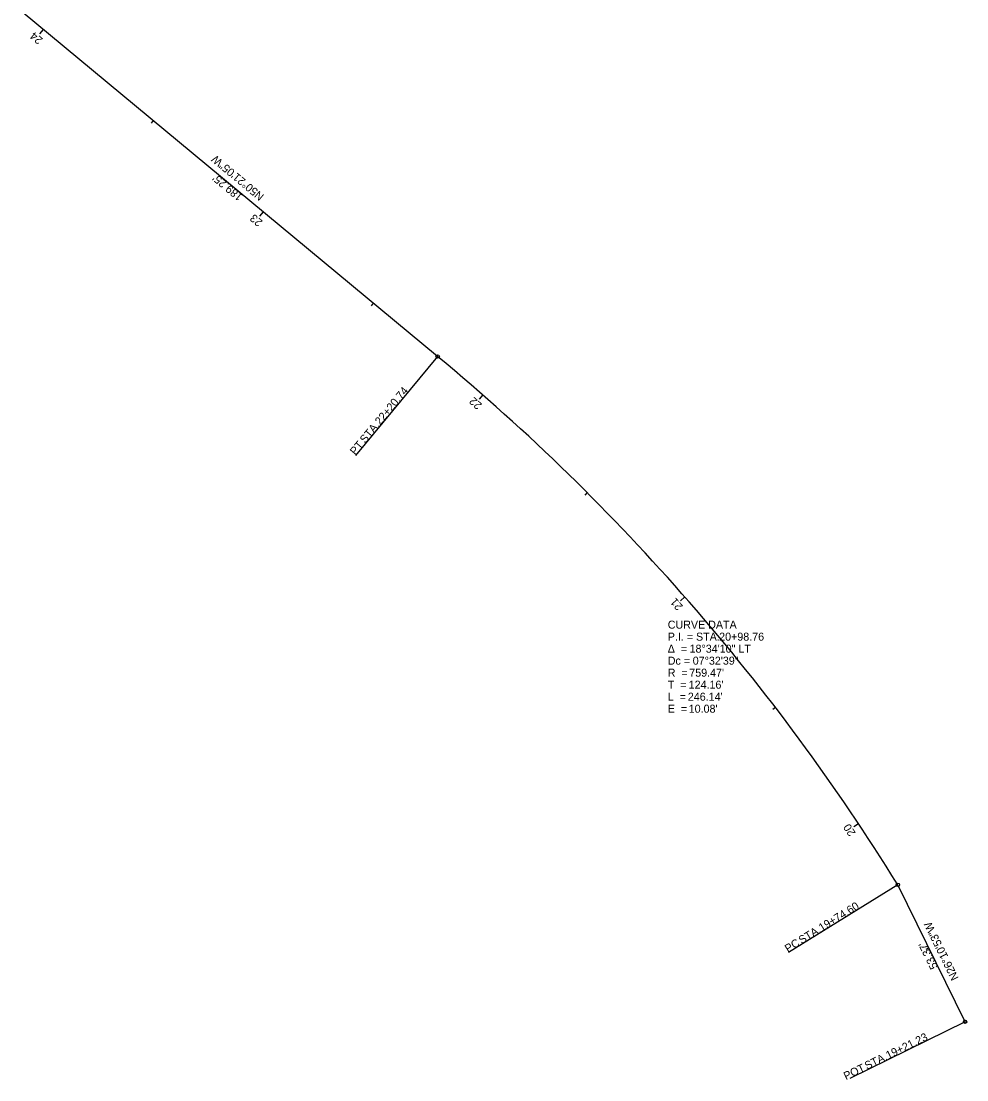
# Model space of a CAD drawing. Extents: x 127563 to 127989, y 300983 to 302508.
# Drawn here: x 127657.7 to 127988.6, y 300983 to 301353.2 of the extents above; entities that cross this region are included whole.
import ezdxf

# ---------------------------------------------------------------- set-up
doc = ezdxf.new("R2010")
doc.units = 0
for name, color, linetype in [('DR_X_Cells', 7, 'Continuous'), ('GK_Drainage_Nodes', 7, 'Continuous'), ('RS_Raster1', 7, 'Continuous'), ('SC_Scratch1', 7, 'Continuous'), ('SV_X_Mon_Cells_Found', 7, 'Continuous'), ('SV_X_Shot_Marker', 7, 'Continuous')]:
    doc.layers.add(name, color=color, linetype=linetype)

msp = doc.modelspace()

# ---------------------------------------------------------------- linework, layer by layer
at = {"layer": 'GK_Drainage_Nodes'}
for p, q in [((127665.41, 301350.34), (127664.13, 301348.8)), ((127703.91, 301318.44), (127703.14, 301317.51)), ((127742.4, 301286.53), (127741.13, 301284.99)), ((127780.9, 301254.63), (127780.14, 301253.71)), ((127819.22, 301222.51), (127817.9, 301221.01)), ((127855.72, 301188.35), (127854.87, 301187.5)), ((127889.9, 301151.87), (127888.39, 301150.55)), ((127921.6, 301113.21), (127920.65, 301112.48)), ((127950.69, 301072.56), (127949.02, 301071.45)), ((127975.28, 301029.12), (127974.2, 301028.59))]:
    msp.add_line(p, q, dxfattribs=at)
at = {"layer": 'SC_Scratch1'}
for p, q in [((127803.43, 301235.96), (127774.72, 301201.31)), ((127964.42, 301051.2), (127926.17, 301027.5)), ((127987.97, 301003.3), (127947.59, 300983.45))]:
    msp.add_line(p, q, dxfattribs=at)
for centre in [(127803.43, 301235.96), (127964.42, 301051.2), (127987.97, 301003.3)]:
    msp.add_circle(centre, 0.6, dxfattribs=at)
at = {"layer": 'SV_X_Shot_Marker'}
for p, q in [((127803.43, 301235.96), (127657.71, 301356.72)), ((127987.97, 301003.3), (127964.42, 301051.2))]:
    msp.add_line(p, q, dxfattribs=at)
msp.add_arc((127318.83, 300651.19), 759.47, 31.78204, 50.35148, dxfattribs=at)

# ---------------------------------------------------------------- texts
at = {"layer": 'DR_X_Cells'}
for s, rotation, p in [("189.25'", 140.3515, (127735.5, 301292.21)), ("53.37'", 116.1813, (127978.51, 301022.46))]:
    msp.add_text(s, height=2.8, rotation=rotation, dxfattribs=at).set_placement(p)
at = {"layer": 'GK_Drainage_Nodes'}
for s, rotation, p in [('24', 140.3515, (127665.48, 301347.04)), ('23', 140.3515, (127742.41, 301283.28)), ('22', 138.7865, (127819.15, 301219.25)), ('21', 131.2423, (127889.41, 301148.64)), ('20', 123.6981, (127949.8, 301069.38))]:
    msp.add_text(s, height=2.8, rotation=rotation, dxfattribs=at).set_placement(p)
at = {"layer": 'RS_Raster1'}
for s, rotation, p in [('N50°21\'05"W', 140.3515, (127742.9, 301292.36)), ('N26°10\'53"W', 116.1813, (127985.81, 301018.57))]:
    msp.add_text(s, height=2.8, rotation=rotation, dxfattribs=at).set_placement(p)
at = {"layer": 'SC_Scratch1'}
for s, rotation, p in [('22+20.74', 50.3515, (127783.34, 301211.78)), (' STA. ', 50.3515, (127777.4, 301204.61)), ('PT', 50.3515, (127774.62, 301201.26)), ('19+74.60', 31.782, (127937.8, 301034.74)), (' STA. ', 31.782, (127929.88, 301029.83)), ('PC', 31.782, (127925.96, 301027.41)), ('19+21.23', 26.1813, (127961.07, 300990.11)), (' STA. ', 26.1813, (127952.7, 300986)), ('POT', 26.1813, (127946.3, 300982.85))]:
    msp.add_text(s, height=2.8, rotation=rotation, dxfattribs=at).set_placement(p)
at = {"layer": 'SV_X_Mon_Cells_Found'}
for s, p in [('CURVE DATA', (127883.93, 301140.78)), ('P.I. = STA. ', (127883.93, 301136.58)), ('20+98.76', (127901.92, 301136.58)), ('18°34\'10" LT', (127891.57, 301132.38)), ('Δ  = ', (127883.93, 301132.38)), ('Dc = ', (127883.93, 301128.18)), ('07°32\'39"', (127892.67, 301128.18)), ('R  = ', (127883.93, 301123.98)), ("759.47'", (127891.46, 301123.98)), ('T  = ', (127883.93, 301119.78)), ("124.16'", (127891.25, 301119.78)), ('L  = ', (127883.93, 301115.58)), ("246.14'", (127890.96, 301115.58)), ('E  = ', (127883.93, 301111.38)), ("10.08'", (127891.27, 301111.38))]:
    msp.add_text(s, height=2.8, dxfattribs=at).set_placement(p)

doc.saveas('drawing.dxf')
